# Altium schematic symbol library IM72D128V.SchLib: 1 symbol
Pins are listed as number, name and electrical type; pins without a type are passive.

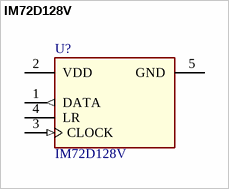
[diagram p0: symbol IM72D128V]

## IM72D128V
designator U?
High Performance Digital XENSIV MEMS Microphone; Manufacturer: Infineon Technologies
pins: 1 DATA (out) "PDM data output", 2 VDD (power) "Power supply", 3 CLOCK (in) "PDM clock input", 4 LR "PDM left/right select", 5 GND (power) "Ground"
